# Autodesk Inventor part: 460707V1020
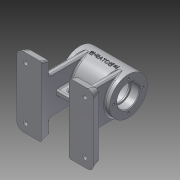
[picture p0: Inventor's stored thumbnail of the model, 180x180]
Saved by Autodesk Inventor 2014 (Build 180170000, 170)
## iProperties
Created: 2016-07
Part Number: 460707V1020
Material: 알루미늄 6061
Document SubType Name: Modeling
Designer: USER
Density: 2.71 g/cm^3
Appearance: 알루미늄 - 평지
Mass: 499.058 g
Surface Area: 540.429 cm^2
Volume: 184.154 cm^3
Author: USER
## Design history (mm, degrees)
sketch "스케치1"
  geometry: C1 r 27 at (0, 0); 1 further point
  constraints: 1 centre point, 1 coincident
  dimensions: "d0" = 54 diameter of C1
extrude "돌출1" new body sketch "스케치1" distance "d1" = 70; taper "d2" = 0 deg
sketch "스케치2"
  geometry: C1 r 27 at (0, 0) reference; C2 r 16 at (0, 0)
  constraints: 1 centre point, 1 coincident
  dimensions: "d3" = 32 diameter of C2
extrude "돌출2" cut sketch "스케치2" distance "d4" = 12; taper "d5" = 0 deg
sketch "스케치3"
  geometry: C1 r 16 at (0, 0) reference; C2 r 14 at (0, 0)
  constraints: 1 centre point, 1 coincident
  dimensions: "d6" = 28 diameter of C2
extrude "돌출3" cut sketch "스케치3" distance "d7" = 2; taper "d8" = 0 deg
sketch "스케치4"
  geometry: C1 r 14 at (0, 0) reference; C2 r 22 at (0, 0)
  constraints: 1 centre point, 1 coincident
  dimensions: "d9" = 44 diameter of C2
extrude "돌출4" cut sketch "스케치4" distance "d10" = 42; taper "d11" = 0 deg
sketch "스케치5"
  geometry: C1 r 27 at (0, 0) reference; C2 r 16 at (0, 0)
  constraints: 1 centre point, 1 coincident
  dimensions: "d12" = 32 diameter of C2
extrude "돌출5" cut sketch "스케치5" distance "d13" = 12; taper "d14" = 0 deg
sketch "스케치6"
  geometry: C1 r 16 at (0, 0) reference; C2 r 14 at (0, 0)
  constraints: 1 centre point, 1 coincident
  dimensions: "d15" = 28 diameter of C2
extrude "돌출6" cut sketch "스케치6" distance "d16" = 12; taper "d17" = 0 deg
sketch "스케치7"
  geometry: C1 r 16 at (0, 0) reference; 1 further point
  constraints: 1 vertical alignment
  dimensions: "d18" = 21 distance of C1.centre point (0, 21)
hole "구멍1" sketch "스케치7" at (0, 21) diameter "d19" = 3.242; stored, may be unused: countersink angle "d23" = 90 deg, drill point angle "d25" = 118 deg; dims "d20" = 8, "d21" = 4, "d22" = 2, "d24" = 10
node "작업 평면1"
node "작업 평면2"
sketch "스케치8"
  geometry: C1 r 5 at (-22, 0); 1 further point
  constraints: 1 centre point, 1 horizontal alignment
  dimensions: "d30" = 10 diameter of C1; "d31" = 22 distance of point (0, 0) C1.centre
extrude "돌출7" join sketch "스케치8" stored distance "d32" = 12; taper "d33" = 0 deg
sketch "스케치9"
  geometry: C1 r 5 at (0, 0) reference; 2 further points
  constraints: 1 coincident
hole "구멍2" sketch "스케치9" at (0, 0) diameter "d34" = 6.188; stored, may be unused: countersink angle "d38" = 90 deg, drill point angle "d40" = 118 deg; dims "d35" = 8, "d36" = 4, "d37" = 2, "d39" = 10
chamfer "모따기1" distance "d42" = 1; stored, may be unused: second distance "d43" = 2, angle "d44" = 45 deg
fillet "모깎기2" dims "d45" = 2
node "작업 평면3"
fillet "모깎기1" dims "d41" = 3
sketch "스케치10"
  geometry: L1 (20, 50)-(-90, 50); L2 (-90, 50)-(-90, -50); L3 (-90, -50)-(20, -50); L4 (20, -50)-(20, 50); L5 (-70, 27)-(-70, -27) reference; L6 (0, -27)-(0, 27) reference; L7 (0, 27)-(-70, 27) reference; 5 further points
  constraints: 8 end point, 3 midpoint, 2 parallel, 1 horizontal, 1 horizontal alignment, 1 perpendicular, 1 vertical alignment, 1 other
  dimensions: "d47" = 110 distance of L3.end L2.end; "d48" = 100 distance of L2.end L1.end
extrude "돌출8" join sketch "스케치10" distance "d49" = 12; taper "d50" = 0 deg
sketch "스케치11"
  geometry: L1 (-20, 50)-(90, 50) reference; L2 (-20, -50)-(-20, 50) reference; L3 (90, -50)-(-20, -50) reference; L4 (90, 50)-(90, -50) reference; L5 (15, 50)-(55, 50); L6 (55, 50)-(55, -50); L7 (55, -50)-(15, -50); L8 (15, -50)-(15, 50); 2 further points
  constraints: 8 end point, 3 point on line, 2 parallel, 1 horizontal, 1 perpendicular
  dimensions: "d51" = 35 distance from line of L5.start L2; "d52" = 35 distance from line of point (55, 50) L4; "d53" = 40 distance between parallel lines of L6 L8
sketch "스케치12"
  geometry: L1 (0, 0)-(110, 0) reference; L2 (110, 0)-(110, 12) reference; L3 (0, 12)-(110, 12) reference; L4 (0, 0)-(7.126, 19.578); L5 (7.126, 19.578)-(0, 19.578); L6 (0, 19.578)-(0, 0); L7 (110, 0)-(103.471, 17.938); L8 (103.471, 17.938)-(110, 17.938); L9 (110, 17.938)-(110, 0); 1 further point
  constraints: 12 end point, 2 parallel, 1 collinear, 1 perpendicular
  dimensions: "d54" = 20 deg angle of L9 L7; "d55" = 17.93768 distance between parallel lines of L1 L8; "d56" = 20 deg angle of L4 L6; "d57" = 19.5778 distance between parallel lines of L1 L5
extrude "돌출9" cut sketch "스케치12" stored distance "d58" = 12; taper "d59" = 0 deg
extrude "돌출10" cut sketch "스케치11" distance "d60" = 12; taper "d61" = 0 deg
sketch "스케치13"
  geometry: L1 (50, -70)-(-50, -70) reference; L2 (50, -58)-(50, -70) reference; L3 (-50, -58)-(50, -58) reference; L4 (-50, -70)-(-50, -58) reference; L5 (-50, -70)-(-50, -42.584); L6 (-50, -42.584)-(-40.021, -42.584); L7 (-40.021, -42.584)-(-50, -70); L8 (50, -70)-(50, -41.761); L9 (50, -41.761)-(39.722, -41.761); L10 (39.722, -41.761)-(50, -70); 1 further point
  constraints: 12 end point, 2 perpendicular, 1 collinear, 1 point on line
  dimensions: "d62" = 20 deg angle of L7 L5; "d63" = 27.41589 distance between parallel lines of L1 L6; "d64" = 20 deg angle of L8 L10; "d65" = 28.23902 distance between parallel lines of L1 L9
extrude "돌출11" cut sketch "스케치13" stored distance "d66" = 120; taper "d67" = 0 deg
node "작업 평면4"
sketch "스케치14"
  geometry: L1 (77, 70)-(77, 6.767); L2 (23, 70)-(23, 6.767); L3 (77, 6.767)-(23, 6.767); L4 (100, 0)-(0, 0) reference; A1 r 27 centre (50, 70) between (77, 70) and (23, 70) reference; A2 r 27 centre (50, 70) between (23, 70) and (77, 70); 1 further point
  constraints: 6 end point, 4 point on circle, 2 tangent, 1 centre point, 1 coincident, 1 concentric, 1 parallel, 1 perpendicular, 1 vertical
  dimensions: "d69" = 6.7668 distance between parallel lines of L4 L3
extrude "돌출12" join sketch "스케치14" distance "d70" = 8; taper "d71" = 0 deg
sketch "스케치15"
  geometry: L1 (-20, 50)-(-20, -50) reference; L2 (55, -50)-(15, -50) reference; L3 (15, 50)-(55, 50) reference; 7 further points
  dimensions: "d72" = 12.5 distance from line of point (-7.5, -37.5) L1; "d73" = 12.5 distance from line of point (-7.5, -37.5) L2; "d74" = 12.5 distance from line of L1 point (-7.5, 37.5); "d75" = 12.5 distance from line of point (-7.5, 37.5) L3
hole "구멍3" sketch "스케치15" at (-7.5, -37.5), (-7.5, 37.5) diameter "d76" = 6; stored, may be unused: countersink angle "d80" = 90 deg, drill point angle "d82" = 118 deg; dims "d77" = 8, "d78" = 10, "d79" = 4, "d81" = 12
sketch "스케치17"
  geometry: L1 (-4, -48)-(4, -48); L2 (-4, -48)-(-4, -25); L3 (4, -48)-(4, -25); L4 (-4, -25)-(4, -25); A1 r 27 centre (0, 0) between (-27, 0) and (27, 0) reference; 3 further points
  constraints: 8 end point, 2 perpendicular, 1 horizontal, 1 midpoint, 1 parallel, 1 point on circle, 1 vertical alignment
  dimensions: "d87" = 8 distance of L1.start L1.end; "d89" = 23 distance between parallel lines of L1 L4; "d90" = 21 distance of point (0, -48) point (0, -27)
extrude "돌출13" join sketch "스케치17" stored distance "d91" = 43; taper "d92" = 0 deg
sketch "스케치18"
  geometry: L1 (40, -21.298)-(0, -21.298) reference; L2 (12, -11.298)-(28, -11.298); L3 (12, -14.798)-(28, -14.798); L4 (28, -7.798)-(12, -7.798); L5 (40, -43.298)-(0, -43.298) reference; A1 r 3.5 centre (12, -11.298) between (12, -7.798) and (12, -14.798); A2 r 3.5 centre (28, -11.298) between (28, -14.798) and (28, -7.798); 4 further points
  constraints: 8 end point, 4 point on circle, 4 tangent, 2 centre point, 2 midpoint, 2 parallel, 1 vertical alignment
  dimensions: "d93" = 7 diameter of A2; "d94" = 23 dimension on A2 A1; "d95" = 32 distance from line of L5 point (20, -11.298)
extrude "돌출14" cut sketch "스케치18" distance "d96" = 43; taper "d97" = 0 deg
sketch "스케치20"
  geometry: L1 (0, 0)-(-15.898, -25.441); L2 (0, 0)-(0, -27.58); L3 (-15.898, -25.441)-(-20.986, -22.262); L4 (-20.986, -22.262)-(-18.336, -18.022); L5 (-18.336, -18.022)-(-13.248, -21.201)
  constraints: 10 end point, 3 perpendicular, 1 point on line, 1 vertical
  dimensions: "d109" = 30 distance of L1.start L1.end; "d110" = 32 deg angle of L2 L1; "d111" = 12 diameter of L4 L1; "d112" = 5 distance between parallel lines of L3 L5
revolve "회전1" sketch "스케치20" stored, may be unused: angle "d113" = 90 deg
sketch "스케치21"
  geometry: C1 r 6 at (0, 0) reference; 2 further points
  constraints: 1 coincident
hole "구멍4" sketch "스케치21" at (0, 0) diameter "d114" = 5.188; stored, may be unused: countersink angle "d118" = 90 deg, drill point angle "d120" = 118 deg; dims "d115" = 8, "d116" = 10, "d117" = 4, "d119" = 12
fillet "모깎기3" dims "d121" = 2
fillet "모깎기4" dims "d122" = 2
fillet "모깎기7" dims "d125" = 2
node "작업 평면5"
sketch "스케치22"
  geometry: L1 (0, 27)-(0, -27) reference; 3 further points
  constraints: 1 horizontal alignment, 1 midpoint, 1 other
  dimensions: "d127" = 35 distance from line of point (35, 0) L1
feature "엠보싱1" sketch "스케치22" dims "d128" = 0.5, "d129" = 0
fillet "모깎기12" dims "d134" = 2
fillet "모깎기13" dims "d135" = 5, "d136" = 10
fillet "모깎기14" dims "d137" = 5, "d138" = 10
fillet "모깎기15" dims "d139" = 5, "d140" = 10
fillet "모깎기16" dims "d141" = 5, "d142" = 10
fillet "모깎기17" dims "d143" = 2
fillet "모깎기18" dims "d144" = 0.3
node "솔리드1"
pattern_circular "원형 패턴1" dims angle "d27" = 360 deg
mirror "대칭1"
mirror "대칭2"
mirror "대칭3"
node "투영된 루프1"
node "투영된 루프2"
other parameters: "d68" = -8, "d126" = 27
